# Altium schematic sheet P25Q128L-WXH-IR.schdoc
size 127 x 101 mm
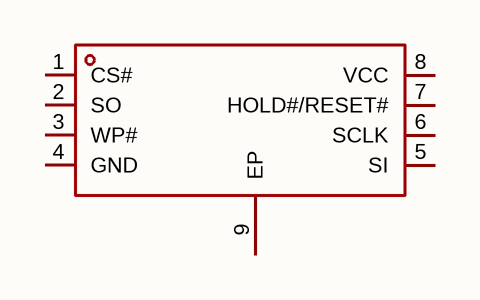
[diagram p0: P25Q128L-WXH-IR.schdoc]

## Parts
U?  p25q128l-wxh-ir  [WSON-8_L6.0-W5.0-P1.27-BL-EP]  (value not drawn)

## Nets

Not connected (* = marked no-connect by the designer): U? 1(CS#) 2(SO) 3(WP#) 4(GND) 5(SI) 6(SCLK) 7(HOLD#/RESET#) 8(VCC) 9(EP)

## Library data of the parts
U? = p25q128l-wxh-ir: 接口类型:SPI;存储容量:128Mbit;时钟频率(fc):85MHz;; Manufacturer: PUYA(普冉); AddInBom: yes; ModelId: 72347fabc1e24788a361efd6527ab939; ModelName: WSON-8_L6.0-W5.0-H0.7-P1.27; ModelTransform: 237.007,196.85,0,90,0,0,0,0,0; Interface: SPI; Clock Frequency: 85MHz; Voltage - Supply: 1.65V~2V; Standby Supply Current: 15uA; Program / Erase Cycles: 100000次; Page Programming Time (Tpp): 1.5ms; Data Retention - TDR (Year): 20年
